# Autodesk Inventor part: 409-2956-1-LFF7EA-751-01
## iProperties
Created: 2010-06
Part Number: 409-2956-1-LFF7EA-751-01
Material: Sch40 CS PIPE SEAMLESS
Description: PIPE
Document SubType Name: Modeling
Designer: S. Boerckel
Engineer: Steve Boerckel
Mass: 958.943 g
Surface Area: 638.46 cm^2
Volume: 122.158 cm^3
Density: 7.85 g/cm^3
Cost Center: 4"
SMR: =<COST CENTER> - <Material>
Length: 6.938 in
Title: 2"
Author: S. Boerckel
Revision Number: B
Subject: DEMIN WATER FORWARDING PUMP SKID-7EA
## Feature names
1. Extrusion1
